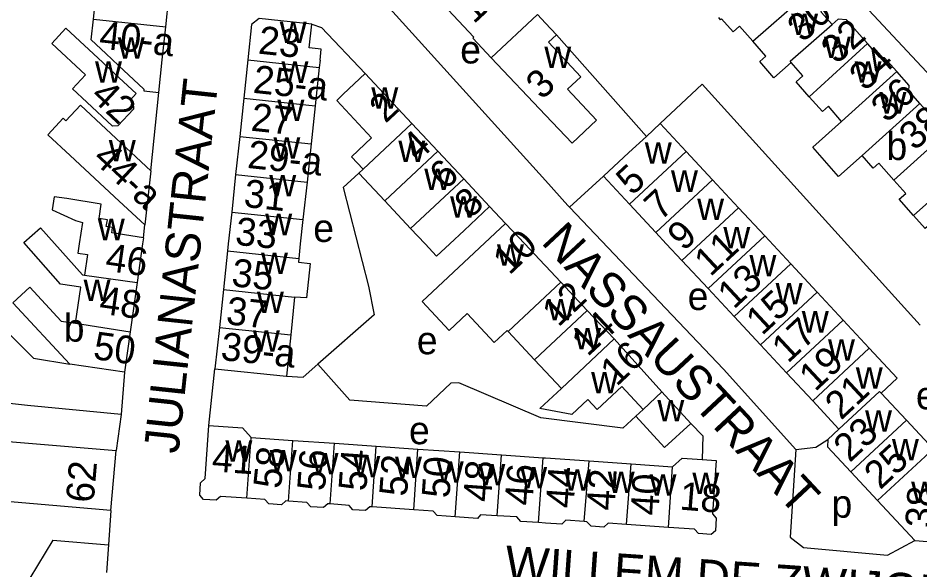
# Model space of a CAD drawing. Extents: x 159261 to 160849, y 382514 to 384534.
# Drawn here: x 160624.3 to 160753.7, y 382953.2 to 383032.4 of the extents above; entities that cross this region are included whole.
import ezdxf

# ---------------------------------------------------------------- set-up
doc = ezdxf.new("R2010")
doc.units = 0
for name, color, linetype in [('BLT_Basislijn', 7, 'Continuous'), ('BLT_Bebouwing', 7, 'Continuous'), ('BLT_Centroide', 7, 'Continuous'), ('BLT_Huisnummer', 7, 'Continuous'), ('BLT_Huisnummer_ tussenligend', 7, 'Continuous'), ('BLT_Huisnummer_reeks', 7, 'Continuous'), ('BLT_Onderverdeling_panden', 7, 'Continuous'), ('BLT_Straatnaam', 7, 'Continuous'), ('BLT_Straatnaam_hoofdweg', 7, 'Continuous')]:
    doc.layers.add(name, color=color, linetype=linetype)

msp = doc.modelspace()

# ---------------------------------------------------------------- linework, layer by layer
at = {"layer": 'BLT_Basislijn'}
for p, q in [((160714.48, 383015.41), (160701.57, 383029.98)), ((160643.39, 383010.48), (160644.52, 383021.7)), ((160703.45, 383005.24), (160708.32, 383009.7)), ((160694.26, 383002.9), (160691.98, 383005.33)), ((160642.32, 383000.83), (160642.52, 383002.72)), ((160622.27, 382987.9), (160626.56, 382983.56)), ((160626.56, 382983.56), (160631.75, 382982.69)), ((160651.7, 382973.91), (160652.59, 382982.06)), ((160639.6, 382981.57), (160639.13, 382975.48)), ((160625.7, 382976.8), (160620.87, 382977.29)), ((160639.13, 382975.48), (160625.7, 382976.8)), ((160639.13, 382975.48), (160638.4, 382970.3)), ((160735.91, 382970.45), (160735.11, 382957.9)), ((160637.67, 382961.71), (160637.32, 382956.76)), ((160629.32, 382957.45), (160621.1, 382943.88)), ((160629.32, 382957.45), (160637.32, 382956.76)), ((160637.32, 382956.76), (160637.04, 382952.81))]:
    msp.add_line(p, q, dxfattribs=at)
for points in [[(160705.76, 383079.87), (160714.48, 383069.58), (160719.65, 383063.88), (160720.38, 383062.82), (160742.22, 383038.75), (160742.22, 383038.49), (160746.42, 383033.51), (160772.56, 383005.52)], [(160700, 383009.05), (160676.77, 383034.77), (160670.95, 383041.01), (160670.1, 383041.92)], [(160666.48, 383031.52), (160667.88, 383031.01), (160674.16, 383024.41)], [(160716.45, 383017.25), (160722.47, 383022.92), (160753.76, 382988.3)], [(160673.24, 383010.14), (160670.99, 383008.06), (160674.61, 382993.9), (160675.45, 382989.8), (160667.37, 382982.7)], [(160700, 383009.05), (160703.23, 383005.48), (160703.45, 383005.24)], [(160703.45, 383005.24), (160725.55, 382981.97), (160735.91, 382970.45)], [(160662.85, 382980.98), (160665.26, 382980.86), (160667.37, 382982.7)], [(160699.34, 382975.03), (160687.56, 382980.01), (160686.45, 382979.98), (160682.94, 382976.67), (160671.95, 382977.55), (160667.37, 382982.7)], [(160712.95, 382975.24), (160711.12, 382973.52), (160699.34, 382975.03)], [(160720.85, 382974.21), (160722.58, 382972.41), (160722.48, 382969.01)], [(160735.91, 382970.45), (160738.78, 382970.8), (160740.53, 382971.92)], [(160735.11, 382957.9), (160737.04, 382956.4), (160749.09, 382955.3)], [(160749.09, 382955.3), (160752.98, 382957.4)]]:
    msp.add_lwpolyline(points, dxfattribs=at)
at = {"layer": 'BLT_Bebouwing'}
for p, q in [((160645.53, 383031.12), (160646.2, 383037.31)), ((160698.86, 383032.9), (160700, 383031.67)), ((160645.02, 383026.4), (160645.53, 383031.12)), ((160700, 383031.67), (160701.57, 383029.98)), ((160741.13, 383031.45), (160741.99, 383032.21)), ((160644.52, 383021.7), (160645.02, 383026.4)), ((160657.3, 383026.37), (160656.72, 383020.89)), ((160667.67, 383026.36), (160667.56, 383025.28)), ((160692.22, 383026.7), (160700, 383018.47)), ((160667.56, 383025.28), (160666.96, 383019.8)), ((160642.4, 383022.17), (160642.37, 383021.93)), ((160642.37, 383021.93), (160644.52, 383021.7)), ((160656.72, 383020.89), (160656.14, 383015.41)), ((160636.97, 383016.46), (160633.29, 383019.89)), ((160666.96, 383019.8), (160666.37, 383014.32)), ((160684.56, 383013.27), (160680.85, 383017.24)), ((160714.48, 383015.41), (160716.45, 383017.25)), ((160716.45, 383017.25), (160720.19, 383013.23)), ((160656.14, 383015.41), (160655.55, 383009.93)), ((160666.37, 383014.32), (160665.81, 383008.83)), ((160688.27, 383009.3), (160684.56, 383013.27)), ((160720.19, 383013.23), (160723.95, 383009.19)), ((160643.39, 383010.48), (160642.52, 383002.72)), ((160673.24, 383010.14), (160673.83, 383010.69)), ((160655.55, 383009.93), (160654.99, 383004.55)), ((160676.95, 383006.16), (160673.24, 383010.14)), ((160691.98, 383005.33), (160688.27, 383009.3)), ((160712.07, 383005.66), (160708.32, 383009.7)), ((160723.95, 383009.19), (160727.7, 383005.16)), ((160665.81, 383008.83), (160665.19, 383003.47)), ((160680.66, 383002.19), (160676.95, 383006.16)), ((160715.82, 383001.63), (160712.07, 383005.66)), ((160665.19, 383003.47), (160664.81, 383000)), ((160694.26, 383002.9), (160682.3, 382991.71)), ((160664.81, 383000), (160664.6, 382997.9)), ((160735.21, 382997.09), (160731.46, 383001.12)), ((160654.39, 382998.98), (160653.8, 382993.41)), ((160719.58, 382997.59), (160723.33, 382993.56)), ((160699.86, 382996.99), (160700, 382996.84)), ((160700, 382996.84), (160702.2, 382994.49)), ((160738.97, 382993.06), (160735.21, 382997.09)), ((160633.58, 382995.52), (160633.89, 382995.47)), ((160641.41, 382994.41), (160640.42, 382987.37)), ((160702.2, 382994.49), (160706.01, 382990.43)), ((160723.33, 382993.56), (160727.09, 382989.53)), ((160653.8, 382993.41), (160653.22, 382987.99)), ((160664.02, 382992.32), (160663.48, 382986.9)), ((160742.72, 382989.02), (160738.97, 382993.06)), ((160706.01, 382990.43), (160709.86, 382986.33)), ((160727.09, 382989.53), (160730.84, 382985.5)), ((160746.47, 382984.99), (160742.72, 382989.02)), ((160640.42, 382987.37), (160639.6, 382981.57)), ((160653.22, 382987.99), (160652.59, 382982.06)), ((160663.48, 382986.9), (160662.85, 382980.98)), ((160709.86, 382986.33), (160716.68, 382978.73)), ((160730.84, 382985.5), (160734.6, 382981.46)), ((160700, 382981.67), (160698.41, 382983.33)), ((160639.6, 382981.57), (160631.75, 382982.69)), ((160702.29, 382979.23), (160700, 382981.67)), ((160734.6, 382981.46), (160738.35, 382977.43)), ((160716.68, 382978.73), (160720.85, 382974.21)), ((160751.78, 382974.68), (160748.15, 382978.57)), ((160738.35, 382977.43), (160742.11, 382973.4)), ((160714, 382976.21), (160712.95, 382975.24)), ((160742.11, 382973.4), (160740.53, 382971.92)), ((160657.77, 382972.19), (160663.76, 382971.77)), ((160663.76, 382971.77), (160669.74, 382971.36)), ((160637.67, 382961.71), (160638.4, 382970.3)), ((160669.74, 382971.36), (160675.73, 382970.94)), ((160675.73, 382970.94), (160681.71, 382970.53)), ((160681.71, 382970.53), (160687.7, 382970.11)), ((160687.7, 382970.11), (160693.68, 382969.69)), ((160693.68, 382969.69), (160699.67, 382969.28)), ((160699.67, 382969.28), (160700, 382969.26)), ((160700, 382969.26), (160706.27, 382968.82)), ((160706.27, 382968.82), (160712.32, 382968.4)), ((160712.32, 382968.4), (160718.23, 382967.99)), ((160743.8, 382967.26), (160747.64, 382963.14)), ((160747.64, 382963.14), (160752.98, 382957.4)), ((160681.11, 382961.81), (160675.12, 382962.23)), ((160717.66, 382959.29), (160711.64, 382959.7)), ((160752.98, 382957.4), (160756.65, 382957.13))]:
    msp.add_line(p, q, dxfattribs=at)
for points in [[(160696.14, 383035.81), (160695.01, 383034.75), (160690.4, 383039.69), (160688.57, 383037.98), (160684.49, 383042.41), (160680.92, 383039.09), (160689.73, 383029.64), (160689.57, 383029.5), (160692.22, 383026.7)], [(160635.16, 383032.23), (160635.66, 383036.8), (160634.02, 383036.98), (160633.97, 383036.49), (160630.5, 383036.86), (160630.73, 383038.97)], [(160741.13, 383031.45), (160739.6, 383033.18), (160739.39, 383034.21), (160737.72, 383036.1)], [(160666.48, 383031.52), (160658.92, 383032.32), (160657.84, 383031.45), (160657.3, 383026.37)], [(160725.27, 383032.26), (160725.14, 383032.15), (160724.86, 383032.47)], [(160729.74, 383029.05), (160727.84, 383031.21), (160726.92, 383030.39), (160725.27, 383032.26)], [(160636.91, 383027.31), (160634.83, 383029.27), (160635.16, 383032.23)], [(160666.12, 383028.11), (160666.48, 383031.52)], [(160746.21, 383028.72), (160743.19, 383032.14), (160741.99, 383032.21)], [(160629.17, 383028.76), (160631.2, 383030.93), (160636.48, 383026.02), (160637.62, 383024.95), (160641.28, 383021.54), (160640.45, 383020.65), (160640.84, 383020.28), (160640.88, 383019.32), (160638.64, 383016.91), (160637.87, 383016.89), (160634.21, 383020.3), (160632.14, 383022.24), (160634.02, 383024.24), (160629.17, 383028.76)], [(160700, 383018.47), (160703.82, 383014.43), (160707.35, 383017.72), (160703.17, 383022.17), (160705.08, 383023.95), (160700.44, 383028.92), (160701.57, 383029.98)], [(160735.27, 383026.02), (160732.78, 383023.83), (160730.75, 383026.13), (160731.63, 383026.9), (160729.74, 383029.05)], [(160750.4, 383024.71), (160748.65, 383026.69), (160747.96, 383026.73), (160746.21, 383028.72)], [(160642.4, 383022.17), (160638.74, 383025.58), (160636.91, 383027.31)], [(160667.67, 383026.36), (160667.84, 383027.93), (160666.12, 383028.11)], [(160737.84, 383021.1), (160735.95, 383023.25), (160736.94, 383024.12), (160735.27, 383026.02)], [(160753.71, 383020.14), (160752.13, 383021.93), (160752.18, 383022.69), (160750.4, 383024.71)], [(160674.16, 383024.41), (160670.99, 383021.46)], [(160680.85, 383017.24), (160674.16, 383024.41)], [(160673.83, 383010.69), (160672.17, 383012.47), (160675.07, 383015.18), (160670.05, 383020.56), (160670.99, 383021.46)], [(160742.5, 383017.55), (160740.59, 383019.72), (160739.73, 383018.96), (160737.84, 383021.1)], [(160633.29, 383019.89), (160631.2, 383017.65), (160630.82, 383018.01), (160628.62, 383015.64), (160631.83, 383012.68), (160638.86, 383006.13), (160642.52, 383002.72)], [(160757.94, 383016.29), (160756.17, 383018.3), (160755.29, 383018.35), (160753.71, 383020.14)], [(160745.42, 383012.66), (160742.07, 383009.65), (160738.38, 383013.84), (160742.5, 383017.55)], [(160643.39, 383010.48), (160636.97, 383016.46)], [(160708.32, 383009.7), (160711.98, 383013.11), (160714.48, 383015.41)], [(160750, 383009.13), (160747.85, 383011.57), (160747.02, 383010.84), (160745.42, 383012.66)], [(160752.82, 383004.05), (160750.76, 383006.39), (160751.69, 383007.21), (160750, 383009.13)], [(160642.32, 383000.83), (160637.77, 383001.55), (160637.89, 383002.32), (160637, 383002.46), (160637.15, 383003.45), (160635.96, 383003.64), (160636.28, 383005.69), (160631.35, 383006.47), (160629.54, 383006.75), (160629.24, 383004.85), (160632.59, 383003.34), (160633.58, 383003.04), (160633.11, 383000), (160632.93, 382998.66), (160634.32, 382998.46), (160633.89, 382995.47)], [(160691.98, 383005.33), (160688.33, 383001.92), (160686.28, 383000), (160684.37, 382998.22), (160682.73, 382999.98), (160680.66, 383002.19)], [(160727.7, 383005.16), (160731.46, 383001.12)], [(160654.99, 383004.55), (160654.5, 383000), (160654.39, 382998.98)], [(160757.37, 383000.67), (160755.37, 383002.94), (160754.49, 383002.16), (160752.82, 383004.05)], [(160694.26, 383002.9), (160697.04, 383000), (160699.86, 382996.99)], [(160632.59, 382988.6), (160633.33, 382993.76), (160630.45, 382994.17), (160625.15, 383000.16), (160627.55, 383002.28), (160633.58, 382995.52)], [(160719.58, 382997.59), (160717.34, 383000), (160715.82, 383001.63)], [(160642.32, 383000.83), (160642.2, 383000), (160641.41, 382994.41)], [(160664.6, 382997.9), (160664.59, 382997.34), (160666.26, 382997.16), (160665.73, 382992.21), (160664.02, 382992.32)], [(160631.75, 382982.69), (160623.59, 382991.52), (160626.02, 382993.77), (160630.52, 382988.9), (160632.59, 382988.6)], [(160637.67, 382961.71), (160602.65, 382964.7), (160588.12, 382953.83), (160582.95, 382960.71), (160583.07, 382960.8), (160576.51, 382969.6), (160581.1, 382973.08), (160581.52, 382972.56), (160590.75, 382979.53), (160591.84, 382992.31)], [(160591.84, 382992.31), (160600.42, 382991.58), (160598.89, 382973.64), (160638.4, 382970.3)], [(160682.3, 382991.71), (160686.19, 382987.54), (160688.77, 382989.96), (160692.65, 382985.8), (160694.5, 382987.53), (160694.63, 382987.39)], [(160698.41, 382983.33), (160694.63, 382987.39)], [(160748.15, 382978.57), (160750.45, 382980.71), (160746.47, 382984.99)], [(160652.59, 382982.06), (160662.85, 382980.98)], [(160714, 382976.21), (160710.94, 382979.51), (160707.43, 382976.21), (160706.08, 382977.64), (160703.78, 382975.49), (160699.21, 382976.34), (160702.29, 382979.23)], [(160712.95, 382975.24), (160717.1, 382970.74), (160720.85, 382974.21)], [(160754.46, 382969.48), (160755.62, 382970.55), (160751.78, 382974.68)], [(160657.16, 382963.46), (160653.39, 382963.72), (160652.76, 382963.17), (160650.96, 382963.31), (160650.41, 382963.92), (160650.53, 382965.7), (160651.2, 382966.31), (160651.7, 382973.91)], [(160651.7, 382973.91), (160656.55, 382973.57), (160657.77, 382972.19)], [(160740.53, 382971.92), (160740.49, 382970.83), (160743.8, 382967.26)], [(160722.48, 382969.01), (160724.49, 382968.87), (160723.97, 382961.25), (160724.51, 382960.63), (160724.4, 382958.8), (160723.77, 382958.26), (160721.96, 382958.39), (160721.38, 382959.04), (160717.66, 382959.29)], [(160718.23, 382967.99), (160719.62, 382969.21), (160722.48, 382969.01)], [(160663.15, 382963.06), (160662.76, 382963.09), (160662.13, 382962.54), (160660.31, 382962.65), (160659.73, 382963.28), (160657.16, 382963.46)], [(160669.14, 382962.65), (160668.8, 382962.68), (160668.16, 382962.12), (160666.34, 382962.24), (160665.79, 382962.87), (160663.15, 382963.06)], [(160675.12, 382962.23), (160674.83, 382962.25), (160674.19, 382961.69), (160672.36, 382961.81), (160671.82, 382962.44), (160669.14, 382962.65)], [(160687.05, 382960.81), (160684.46, 382961.01), (160683.89, 382961.61), (160681.11, 382961.81)], [(160693.08, 382960.94), (160690.67, 382961.07), (160690.25, 382960.58), (160687.05, 382960.81)], [(160699.02, 382959.98), (160696.49, 382960.15), (160695.89, 382960.79), (160693.08, 382960.94)], [(160700, 382959.91), (160699.02, 382959.98)], [(160705.56, 382960.13), (160702.95, 382960.31), (160702.33, 382959.75), (160700, 382959.91)], [(160711.64, 382959.7), (160709, 382959.88), (160708.36, 382959.33), (160706.56, 382959.45), (160705.96, 382960.1), (160705.56, 382960.13)]]:
    msp.add_lwpolyline(points, dxfattribs=at)
at = {"layer": 'BLT_Onderverdeling_panden'}
for p, q in [((160729.74, 383029.05), (160737.72, 383036.1)), ((160698.86, 383032.9), (160692.22, 383026.7)), ((160635.16, 383032.23), (160645.53, 383031.12)), ((160737.84, 383021.1), (160746.21, 383028.72)), ((160742.5, 383017.55), (160750.4, 383024.71)), ((160656.72, 383020.89), (160666.96, 383019.8)), ((160745.42, 383012.66), (160753.71, 383020.14)), ((160673.83, 383010.69), (160680.85, 383017.24)), ((160750, 383009.13), (160757.94, 383016.29)), ((160656.14, 383015.41), (160666.37, 383014.32)), ((160676.95, 383006.16), (160684.56, 383013.27)), ((160712.07, 383005.66), (160720.19, 383013.23)), ((160752.82, 383004.05), (160761.27, 383011.66)), ((160655.55, 383009.93), (160665.81, 383008.83)), ((160680.66, 383002.19), (160688.27, 383009.3)), ((160715.82, 383001.63), (160723.95, 383009.19)), ((160719.58, 382997.59), (160727.7, 383005.16)), ((160654.99, 383004.55), (160665.19, 383003.47)), ((160723.33, 382993.56), (160731.46, 383001.12)), ((160654.39, 382998.98), (160664.6, 382997.9)), ((160727.09, 382989.53), (160735.21, 382997.09)), ((160633.89, 382995.47), (160641.41, 382994.41)), ((160694.63, 382987.39), (160702.2, 382994.49)), ((160653.8, 382993.41), (160664.02, 382992.32)), ((160730.84, 382985.5), (160738.97, 382993.06)), ((160700, 382984.82), (160706.01, 382990.43)), ((160632.59, 382988.6), (160640.42, 382987.37)), ((160734.6, 382981.46), (160742.72, 382989.02)), ((160653.22, 382987.99), (160663.48, 382986.9)), ((160702.29, 382979.23), (160709.86, 382986.33)), ((160698.41, 382983.33), (160700, 382984.82)), ((160738.35, 382977.43), (160746.47, 382984.99)), ((160714, 382976.21), (160716.68, 382978.73)), ((160751.78, 382974.68), (160743.8, 382967.26)), ((160657.16, 382963.46), (160657.77, 382972.19)), ((160663.15, 382963.06), (160663.76, 382971.77)), ((160669.14, 382962.65), (160669.74, 382971.36)), ((160675.12, 382962.23), (160675.73, 382970.94)), ((160681.11, 382961.81), (160681.71, 382970.53)), ((160687.05, 382960.81), (160687.7, 382970.11)), ((160693.08, 382960.94), (160693.68, 382969.69)), ((160699.02, 382959.98), (160699.67, 382969.28)), ((160754.46, 382969.48), (160747.64, 382963.14)), ((160705.56, 382960.13), (160706.27, 382968.82)), ((160711.64, 382959.7), (160712.32, 382968.4)), ((160717.66, 382959.29), (160718.23, 382967.99))]:
    msp.add_line(p, q, dxfattribs=at)
for points in [[(160735.27, 383026.02), (160735.13, 383026.18), (160741.13, 383031.45)], [(160657.3, 383026.37), (160667.56, 383025.28)], [(160748.15, 382978.57), (160747.94, 382978.8), (160742.11, 382973.4)]]:
    msp.add_lwpolyline(points, dxfattribs=at)

# ---------------------------------------------------------------- texts
at = {"layer": 'BLT_Centroide'}
for s, p in [('w', (160735.25, 383029.97)), ('w', (160661.88, 383028.81)), ('w', (160739.96, 383026.66)), ('w', (160638.64, 383026.56)), ('e', (160687.77, 383025.87)), ('w', (160699.84, 383025.23)), ('w', (160635.38, 383023.12)), ('w', (160662.13, 383023.09)), ('w', (160744.36, 383023.12)), ('w', (160675.02, 383019.38)), ('w', (160661.55, 383017.59)), ('w', (160747.92, 383018.69)), ('b', (160748.93, 383012.02)), ('w', (160637.36, 383011.81)), ('w', (160660.97, 383012.22)), ('w', (160678.9, 383011.72)), ('w', (160714.26, 383011.47)), ('w', (160682.61, 383007.72)), ('w', (160718.01, 383007.44)), ('w', (160660.38, 383006.81)), ('w', (160686.32, 383003.75)), ('w', (160721.77, 383003.41)), ('w', (160659.8, 383001.22)), ('w', (160635.78, 383000.5)), ('e', (160666.69, 383000.25)), ('w', (160725.52, 382999.34)), ('w', (160693.05, 382996.84)), ('w', (160659.2, 382995.66)), ('w', (160729.27, 382995.31)), ('w', (160633.74, 382991.77)), ('e', (160720.41, 382990.48)), ('w', (160733.03, 382991.28)), ('w', (160658.61, 382990.06)), ('w', (160700.28, 382989)), ('b', (160630.89, 382985.95)), ('w', (160736.78, 382987.25)), ('w', (160658.03, 382984.5)), ('e', (160681.55, 382984.13)), ('w', (160704.12, 382984.84)), ('w', (160740.54, 382983.22)), ('w', (160744.53, 382979.19)), ('w', (160706.55, 382978.53)), ('e', (160753.15, 382976.23)), ('w', (160716.06, 382974.51)), ('w', (160745.86, 382973.03)), ('e', (160680.43, 382971.22)), ('w', (160654.09, 382968.7)), ('w', (160749.71, 382968.91)), ('w', (160660.45, 382967.31)), ('w', (160666.45, 382966.91)), ('w', (160672.44, 382966.48)), ('w', (160678.42, 382966.38)), ('w', (160684.41, 382965.7)), ('w', (160690.38, 382965.33)), ('w', (160696.38, 382964.89)), ('w', (160702.64, 382964.55)), ('w', (160708.94, 382964.23)), ('w', (160714.94, 382963.84)), ('w', (160721.08, 382964.08)), ('w', (160752.47, 382962.78)), ('p', (160741.04, 382960.68))]:
    msp.add_text(s, height=4, dxfattribs=at).set_placement(p)
at = {"layer": 'BLT_Huisnummer'}
for s, rotation, p in [('1', 42.9922, (160689.72, 383031.45)), ('30', 41.418, (160736.92, 383028.77)), ('23', 353.9301, (160658.69, 383027.3)), ('34', 41.4177, (160745.82, 383021.78)), ('3', 42.9743, (160699.51, 383020.54)), ('42', 317.0101, (160634.54, 383020.99)), ('2', 43.0581, (160677.05, 383017.18)), ('27', 353.9336, (160657.64, 383016.24)), ('38', 41.381, (160752.96, 383013.23)), ('6', 43.0547, (160685.66, 383007.57)), ('5', 42.9465, (160712.45, 383006.79)), ('31', 353.9349, (160656.61, 383005.3)), ('9', 42.9455, (160719.82, 382998.81)), ('10', 43.482, (160694.81, 382995.38)), ('46', 351.9589, (160636.73, 382996.14)), ('35', 353.935, (160654.86, 382993.92)), ('13', 42.9504, (160727.02, 382990.48)), ('48', 351.9589, (160635.86, 382990.01)), ('12', 43.0552, (160701.84, 382987.92)), ('17', 42.945, (160734.79, 382982.73)), ('16', 43.004, (160710.2, 382979.4)), ('21', 42.831, (160742.41, 382974.58)), ('41', 355.9212, (160652.07, 382967.33)), ('58', 83.945, (160662.04, 382964.74)), ('25', 42.9342, (160748.03, 382964.59)), ('52', 85.9176, (160680.13, 382963.66)), ('48', 85.9201, (160692.18, 382962.85)), ('44', 85.922, (160704.02, 382961.96)), ('40', 86.8223, (160716.21, 382960.94)), ('18', 355.3937, (160719.16, 382961.85)), ('38', 86.0848, (160755.58, 382959.13))]:
    msp.add_text(s, height=4, rotation=rotation, dxfattribs=at).set_placement(p)
at = {"layer": 'BLT_Huisnummer_ tussenligend'}
for s, rotation, p in [('32', 41.418, (160741.77, 383025.65)), ('36', 41.4177, (160748.94, 383017.24)), ('4', 43.0581, (160681.73, 383011.69)), ('8', 43.0547, (160689.26, 383003.51)), ('7', 42.9465, (160716.5, 383003.18)), ('33', 353.9349, (160655.38, 382999.87)), ('11', 42.9455, (160723.66, 382995.16)), ('37', 353.935, (160654.07, 382988.45)), ('15', 42.9504, (160731.08, 382986.72)), ('14', 43.0552, (160706.05, 382983.69)), ('50', 351.9589, (160634.99, 382983.47)), ('19', 42.945, (160738.7, 382978.67)), ('23', 42.831, (160743.64, 382968.49)), ('56', 85.9176, (160668.36, 382964.43)), ('54', 85.9176, (160674.29, 382964.42)), ('50', 85.9201, (160686.22, 382963.4)), ('46', 85.922, (160698.12, 382962.33)), ('42', 86.8223, (160709.9, 382961.63))]:
    msp.add_text(s, height=4, rotation=rotation, dxfattribs=at).set_placement(p)
at = {"layer": 'BLT_Huisnummer_reeks'}
for s, rotation, p in [('40-a', 353.9399, (160635.87, 383028.02)), ('25-a', 353.9301, (160657.95, 383021.67)), ('29-a', 353.9336, (160657.14, 383010.89)), ('44-a', 317.0188, (160634.86, 383012)), ('39-a', 353.9301, (160653.3, 382983.33)), ('62', 85.1109, (160635.17, 382962.72))]:
    msp.add_text(s, height=4, rotation=rotation, dxfattribs=at).set_placement(p)
at = {"layer": 'BLT_Straatnaam'}
for s, height, rotation, p in [('JULIANASTRAAT', 4.9999, 83.9065, (160647.34, 382969.77)), ('NASSAUSTRAAT', 5, 313.044, (160699.25, 383000.13)), ('WILLEM DE ZWIJGERSTRAAT', 5, 356.041, (160694.06, 382951.69))]:
    msp.add_text(s, height=height, rotation=rotation, dxfattribs=at).set_placement(p)
at = {"layer": 'BLT_Straatnaam_hoofdweg'}
msp.add_text('MAURITSSTRAAT', height=8, rotation=312.175, dxfattribs=at).set_placement((160699.78, 383091.8))

doc.saveas('drawing.dxf')
